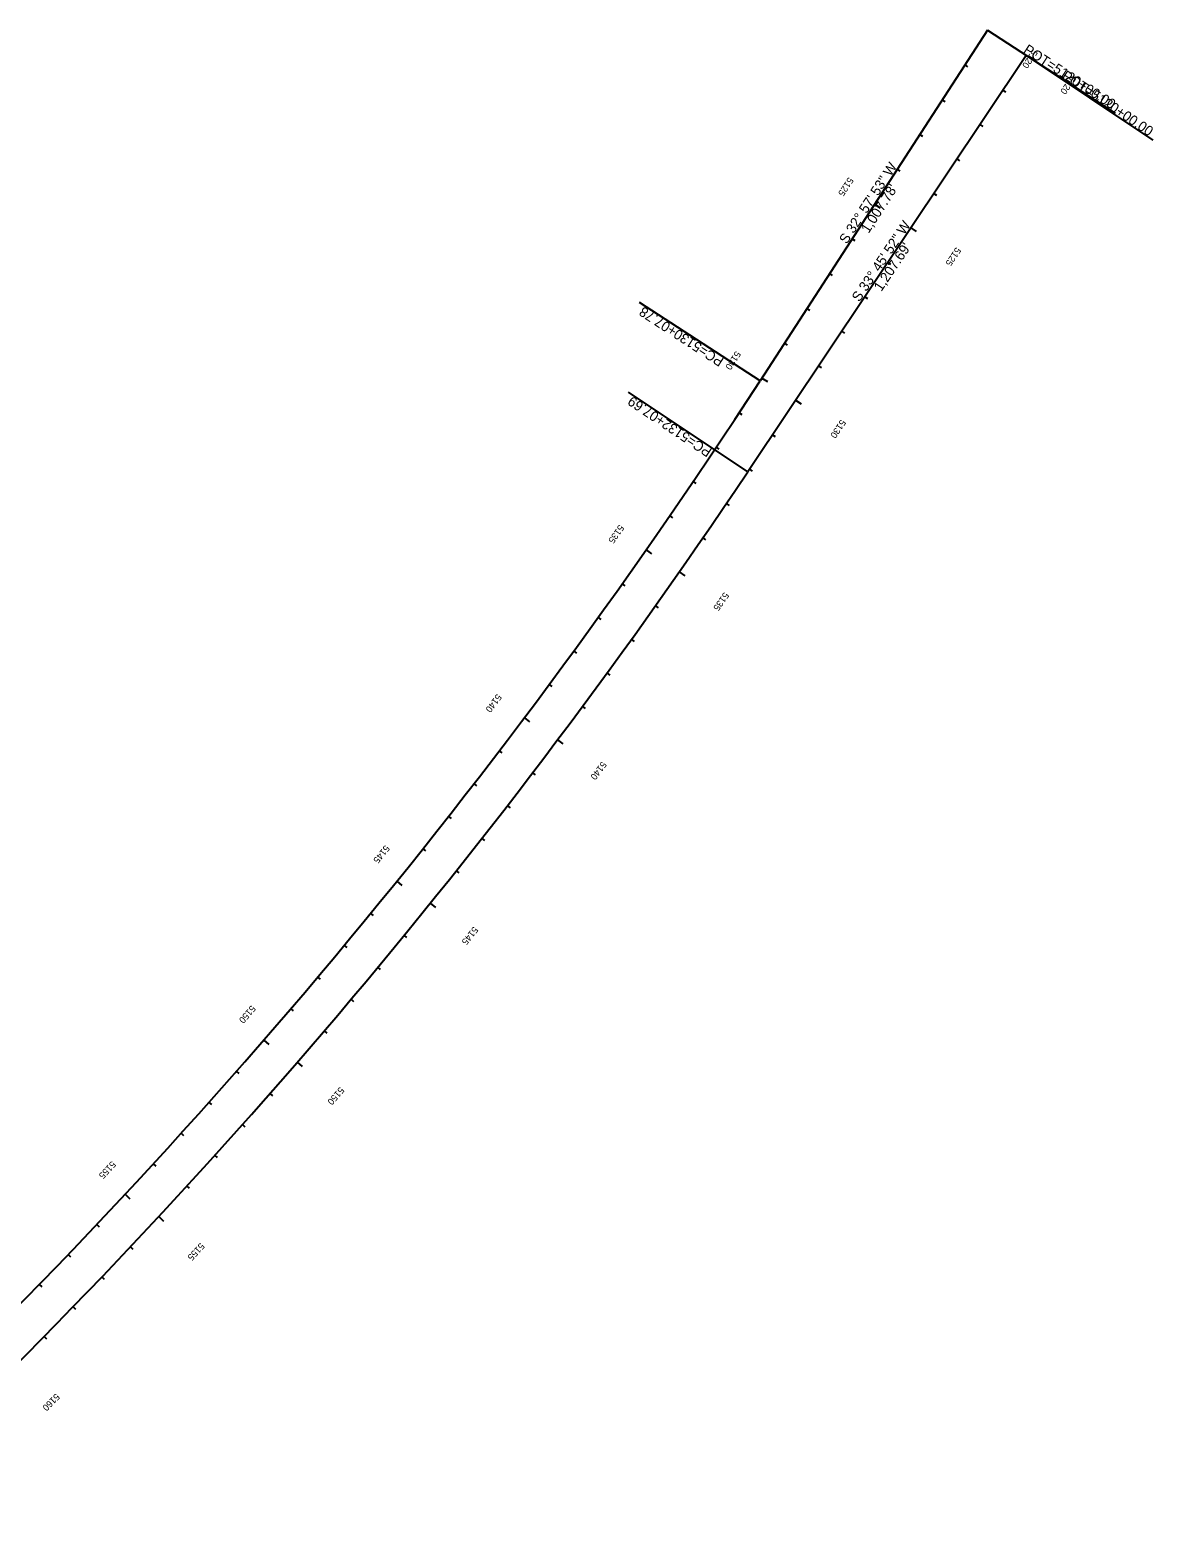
# Model space of a CAD drawing. Extents: x 2160877 to 2175861, y 601747 to 617724.
# Drawn here: x 2173154 to 2175861, y 614087 to 617724 of the extents above; entities that cross this region are included whole.
import ezdxf

# ---------------------------------------------------------------- set-up
doc = ezdxf.new("R2010")
doc.units = 0
for name, color, linetype in [('RD_HC_Cl', 7, 'Continuous'), ('RD_HC_Data', 7, 'Continuous'), ('RD_HC_Data_Tic', 7, 'Continuous'), ('RD_HC_TX_StaOther', 7, 'Continuous')]:
    doc.layers.add(name, color=color, linetype=linetype)

msp = doc.modelspace()

# ---------------------------------------------------------------- linework, layer by layer
at = {"layer": 'RD_HC_Cl'}
for p, q in [((2175462.5, 617723.5), (2174914.1, 616878)), ((2175555.6, 617662.2), (2174884.4, 616658.2))]:
    msp.add_line(p, q, dxfattribs=at)
for radius, end in [(14276, 327.03525), (14372, 326.23563)]:
    msp.add_arc((2162936.5, 624645.9), radius, 312.71947, end, dxfattribs=at)
at = {"layer": 'RD_HC_Data'}
for p, q in [((2175462.5, 617723.5), (2175770.9, 617523.5)), ((2175555.6, 617662.2), (2175861.2, 617457.9)), ((2174914.1, 616878), (2174623.8, 617066.3)), ((2174884.4, 616658.2), (2174596.7, 616850.5))]:
    msp.add_line(p, q, dxfattribs=at)
at = {"layer": 'RD_HC_Data_Tic'}
for p, q in [((2175462.5, 617723.5), (2175475.9, 617714.8)), ((2175555.6, 617662.2), (2175568.9, 617653.3)), ((2175408.1, 617639.6), (2175414.8, 617635.3)), ((2175353.7, 617555.7), (2175360.4, 617551.4)), ((2175500, 617579.1), (2175506.6, 617574.7)), ((2175444.4, 617496), (2175451.1, 617491.5)), ((2175299.2, 617471.8), (2175306, 617467.5)), ((2175388.8, 617412.8), (2175395.5, 617408.4)), ((2175244.8, 617387.9), (2175251.5, 617383.6)), ((2175190.4, 617304), (2175203.8, 617295.3)), ((2175333.3, 617329.7), (2175339.9, 617325.3)), ((2175277.7, 617246.6), (2175291, 617237.7)), ((2175136, 617220.1), (2175142.7, 617215.8)), ((2175222.1, 617163.4), (2175228.8, 617159)), ((2175081.6, 617136.2), (2175088.3, 617131.9)), ((2175166.5, 617080.3), (2175173.2, 617075.9)), ((2175027.2, 617052.3), (2175033.9, 617048)), ((2175110.9, 616997.2), (2175117.6, 616992.7)), ((2174972.8, 616968.4), (2174979.5, 616964.1)), ((2175055.4, 616914), (2175062, 616909.6)), ((2174918.4, 616884.5), (2174931.8, 616875.8)), ((2174999.8, 616830.9), (2175013.1, 616822)), ((2174863.7, 616800.8), (2174870.4, 616796.4)), ((2174808.5, 616717.4), (2174815.1, 616713)), ((2174944.2, 616747.8), (2174950.9, 616743.3)), ((2174888.6, 616664.6), (2174895.3, 616660.2)), ((2174752.6, 616634.5), (2174759.2, 616630)), ((2174832.8, 616581.7), (2174839.4, 616577.2)), ((2174696.2, 616551.9), (2174702.8, 616547.4)), ((2174776.4, 616499.1), (2174783, 616494.6)), ((2174639.2, 616469.7), (2174652.3, 616460.6)), ((2174581.7, 616387.9), (2174588.2, 616383.3)), ((2174719.4, 616416.9), (2174732.6, 616407.7)), ((2174661.9, 616335.1), (2174668.4, 616330.5)), ((2174523.5, 616306.6), (2174530, 616301.9)), ((2174603.8, 616253.7), (2174610.3, 616249.1)), ((2174464.8, 616225.6), (2174471.3, 616220.9)), ((2174545.1, 616172.8), (2174551.6, 616168)), ((2174405.6, 616145.1), (2174412, 616140.3)), ((2174345.8, 616064.9), (2174358.5, 616055.3)), ((2174485.9, 616092.2), (2174492.3, 616087.4)), ((2174426.1, 616012), (2174438.9, 616002.4)), ((2174285.4, 615985.2), (2174291.7, 615980.4)), ((2174365.7, 615932.3), (2174372.1, 615927.5)), ((2174224.4, 615906), (2174230.7, 615901.1)), ((2174304.8, 615853), (2174311.2, 615848.1)), ((2174162.9, 615827.1), (2174169.2, 615822.2)), ((2174243.4, 615774.1), (2174249.7, 615769.2)), ((2174100.9, 615748.7), (2174107.1, 615743.7)), ((2174038.3, 615670.7), (2174050.7, 615660.6)), ((2174181.4, 615695.7), (2174187.6, 615690.7)), ((2173975.1, 615593.2), (2173981.3, 615588.1)), ((2174118.8, 615617.6), (2174131.3, 615607.6)), ((2173911.5, 615516), (2173917.6, 615510.9)), ((2174055.7, 615540), (2174061.9, 615535)), ((2173992.1, 615462.9), (2173998.3, 615457.8)), ((2173847.2, 615439.4), (2173853.3, 615434.2)), ((2173927.9, 615386.2), (2173934.1, 615381)), ((2173782.5, 615363.2), (2173788.6, 615358)), ((2173863.2, 615309.9), (2173869.3, 615304.7)), ((2173717.2, 615287.5), (2173729.3, 615277)), ((2173798, 615234.1), (2173810.1, 615223.7)), ((2173651.4, 615212.2), (2173657.4, 615206.9)), ((2173732.3, 615158.8), (2173738.3, 615153.5)), ((2173585, 615137.3), (2173591, 615132)), ((2173666, 615083.9), (2173672, 615078.6)), ((2173518.2, 615063), (2173524.1, 615057.6)), ((2173599.2, 615009.5), (2173605.1, 615004.1)), ((2173450.8, 614989.1), (2173456.7, 614983.7)), ((2173531.9, 614935.5), (2173537.8, 614930.1)), ((2173382.9, 614915.7), (2173394.6, 614904.8)), ((2173464.1, 614862), (2173475.8, 614851.1)), ((2173314.5, 614842.8), (2173320.3, 614837.3)), ((2173395.8, 614789), (2173401.6, 614783.5)), ((2173245.5, 614770.3), (2173251.3, 614764.8)), ((2173326.9, 614716.5), (2173332.7, 614711)), ((2173176.1, 614698.3), (2173181.8, 614692.8)), ((2173257.6, 614644.4), (2173263.3, 614638.9)), ((2173187.7, 614572.9), (2173193.4, 614567.3))]:
    msp.add_line(p, q, dxfattribs=at)

# ---------------------------------------------------------------- texts
at = {"layer": 'RD_HC_Data'}
for s, rotation, p in [('POT=5120+00.00', 327.0352, (2175547.5, 617670.8)), ('POT=5120+00.00', 326.2356, (2175639.8, 617608.3)), ('PC=5130+07.78', 147.0352, (2174829.1, 616930.7)), ('PC=5132+07.69', 146.2356, (2174800.1, 616712.2))]:
    msp.add_text(s, height=24, rotation=rotation, dxfattribs=at).set_placement(p)
at = {"layer": 'RD_HC_TX_StaOther'}
for s, height, rotation, p in [('5120', 16, 237.0352, (2175571.3, 617678.1)), ('5120', 16, 236.2356, (2175663.7, 617615.3)), ('S 32%%d 57\' 53" W', 24, 57.0352, (2175123.3, 617206)), ('5125', 16, 237.0352, (2175127.4, 617369.9)), ("1,007.78'", 24, 57.0352, (2175175.9, 617232)), ('S 33%%d 45\' 52" W', 24, 56.2356, (2175153.6, 617066.4)), ("1,207.69'", 24, 56.2356, (2175206.6, 617091.6)), ('5125', 16, 236.2356, (2175386.8, 617201.1)), ('5130', 16, 237.0352, (2174855.6, 616950.8)), ('5130', 16, 236.2356, (2175109.2, 616785.8)), ('5135', 16, 235.0597, (2174574.6, 616531.9)), ('5135', 16, 235.0703, (2174827.6, 616369.2)), ('5140', 16, 233.053, (2174279.7, 616123.7)), ('5140', 16, 233.077, (2174532.8, 615961)), ('5145', 16, 231.0463, (2174010.2, 615759.2)), ('5145', 16, 231.0836, (2174223.4, 615562.5)), ('5150', 16, 229.0396, (2173687.4, 615372.7)), ('5150', 16, 229.0903, (2173901, 615175.8)), ('5155', 16, 227.0328, (2173350.7, 614997)), ('5155', 16, 227.097, (2173564.6, 614799.8)), ('5160', 16, 225.1037, (2173216, 614436.4))]:
    msp.add_text(s, height=height, rotation=rotation, dxfattribs=at).set_placement(p)

doc.saveas('drawing.dxf')
